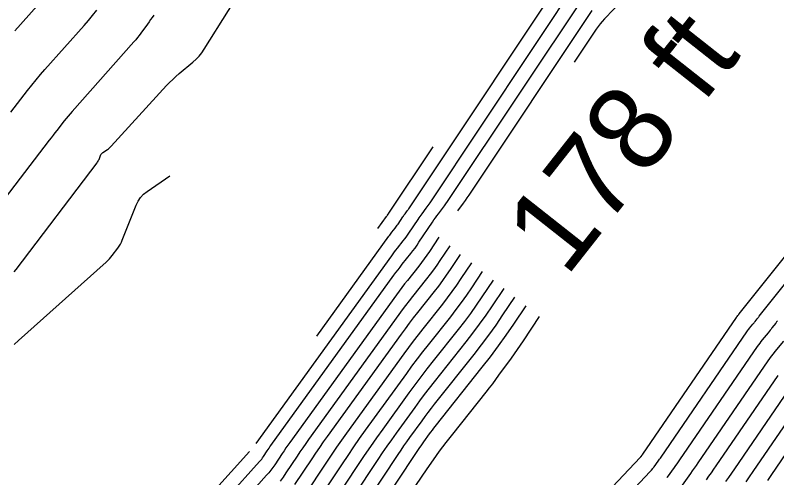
# Model space of a CAD drawing. Extents: x 7585033 to 7595090, y 547091 to 553471.
# Drawn here: x 7587211.1 to 7587267.7, y 547852.6 to 547887 of the extents above; entities that cross this region are included whole.
import ezdxf

# ---------------------------------------------------------------- set-up
doc = ezdxf.new("R2010")
doc.units = 0
for name, color, linetype in [('E_TERR_DSPLAY_GeneralTx', 7, 'Continuous'), ('E_TERR_DSPLAY_MajContour', 7, 'Continuous'), ('E_TERR_DSPLAY_MinContour', 7, 'Continuous')]:
    doc.layers.add(name, color=color, linetype=linetype)

msp = doc.modelspace()

# ---------------------------------------------------------------- linework, layer by layer
at = {"layer": 'E_TERR_DSPLAY_MajContour'}
for points in [[(7587253.285, 547890.138), (7587241.908, 547873.053), (7587241.836, 547872.947), (7587241.763, 547872.843), (7587241.689, 547872.739), (7587241.613, 547872.637), (7587241.306, 547872.229), (7587241.23, 547872.126), (7587241.156, 547872.023), (7587241.082, 547871.918), (7587241.011, 547871.813), (7587240.324, 547870.785), (7587240.226, 547870.641), (7587240.124, 547870.499), (7587240.02, 547870.359), (7587239.912, 547870.221), (7587239.477, 547869.673), (7587239.369, 547869.536), (7587239.262, 547869.397), (7587239.157, 547869.257), (7587239.054, 547869.116), (7587228.97, 547855.173)], [(7587211.064, 547885.809), (7587212.715, 547887.662)], [(7587211.012, 547862.513), (7587211.35, 547862.826), (7587217.852, 547868.647), (7587217.976, 547868.763), (7587218.094, 547868.884), (7587218.205, 547869.011), (7587218.311, 547869.144), (7587218.722, 547869.685), (7587218.82, 547869.823), (7587218.907, 547869.966), (7587218.985, 547870.116), (7587219.052, 547870.271), (7587220.075, 547872.862), (7587220.22, 547873.165), (7587220.405, 547873.437), (7587220.63, 547873.677), (7587220.894, 547873.886), (7587222.596, 547875.043)], [(7587231.884, 547852.131), (7587233.158, 547854.048), (7587233.438, 547854.467), (7587233.723, 547854.882), (7587234.013, 547855.295), (7587234.306, 547855.704), (7587239.794, 547863.294), (7587240.091, 547863.699), (7587240.392, 547864.101), (7587240.698, 547864.499), (7587241.009, 547864.894), (7587242.26, 547866.466), (7587242.568, 547866.863), (7587242.868, 547867.265), (7587243.16, 547867.673), (7587243.443, 547868.088), (7587244.199, 547869.219)], [(7587234.41, 547848.472), (7587238.072, 547853.985), (7587238.402, 547854.477), (7587238.737, 547854.966), (7587239.078, 547855.452), (7587239.423, 547855.934), (7587240.812, 547857.856), (7587241.163, 547858.334), (7587241.518, 547858.808), (7587241.879, 547859.278), (7587242.246, 547859.744), (7587244.607, 547862.712), (7587245.117, 547863.366), (7587245.612, 547864.031), (7587246.094, 547864.706), (7587246.562, 547865.39), (7587247.422, 547866.678)], [(7587268.184, 547862.77), (7587267.553, 547862.007), (7587267.415, 547861.836), (7587267.281, 547861.663), (7587267.151, 547861.487), (7587267.025, 547861.307), (7587261.834, 547853.735), (7587261.696, 547853.535), (7587261.556, 547853.336), (7587261.415, 547853.138), (7587261.273, 547852.941), (7587260.529, 547851.919)], [(7587270.134, 547856.995), (7587267.306, 547852.87), (7587267, 547852.428)], [(7587228.495, 547854.582), (7587225.771, 547851.56), (7587225.725, 547851.507), (7587225.681, 547851.454), (7587225.638, 547851.399), (7587225.597, 547851.344), (7587225.434, 547851.118), (7587225.394, 547851.062), (7587225.353, 547851.005), (7587225.313, 547850.949), (7587225.272, 547850.893), (7587213.854, 547834.973), (7587213.662, 547834.713), (7587213.464, 547834.46), (7587213.258, 547834.212), (7587213.046, 547833.969), (7587212.181, 547833.011), (7587211.966, 547832.77), (7587211.754, 547832.527), (7587211.545, 547832.282), (7587211.338, 547832.034), (7587205.238, 547824.638)]]:
    msp.add_lwpolyline(points, dxfattribs=at)
at = {"layer": 'E_TERR_DSPLAY_MinContour'}
for points in [[(7587233.505, 547863.154), (7587238.869, 547870.572), (7587238.924, 547870.647), (7587238.98, 547870.721), (7587239.036, 547870.795), (7587239.094, 547870.868), (7587239.325, 547871.159), (7587239.383, 547871.233), (7587239.438, 547871.307), (7587239.492, 547871.383), (7587239.545, 547871.46), (7587239.91, 547872.006), (7587239.948, 547872.062), (7587239.987, 547872.118), (7587240.026, 547872.173), (7587240.067, 547872.227), (7587240.23, 547872.444), (7587240.27, 547872.499), (7587240.31, 547872.554), (7587240.349, 547872.61), (7587240.387, 547872.666), (7587252.955, 547891.539)], [(7587258.388, 547890.774), (7587257.674, 547889.983), (7587257.485, 547889.77), (7587257.301, 547889.553), (7587257.12, 547889.332), (7587256.944, 547889.108), (7587256.196, 547888.139), (7587256.045, 547887.948), (7587255.888, 547887.761), (7587255.726, 547887.578), (7587255.56, 547887.4), (7587254.884, 547886.694), (7587254.719, 547886.514), (7587254.563, 547886.328), (7587254.415, 547886.135), (7587254.275, 547885.935), (7587252.643, 547883.483)], [(7587211.013, 547867.91), (7587211.158, 547868.093), (7587217.173, 547876.01), (7587217.217, 547876.072), (7587217.257, 547876.137), (7587217.291, 547876.204), (7587217.322, 547876.273), (7587217.434, 547876.557), (7587217.466, 547876.625), (7587217.507, 547876.685), (7587217.557, 547876.739), (7587217.616, 547876.785), (7587217.946, 547877.009), (7587218.02, 547877.063), (7587218.091, 547877.121), (7587218.158, 547877.183), (7587218.222, 547877.248), (7587222.344, 547881.746), (7587222.569, 547881.983), (7587222.801, 547882.212), (7587223.041, 547882.433), (7587223.289, 547882.646), (7587224.295, 547883.482), (7587224.536, 547883.7), (7587224.758, 547883.934), (7587224.961, 547884.186), (7587225.144, 547884.455), (7587228.745, 547890.212)], [(7587226.897, 547851.217), (7587229.255, 547853.833), (7587229.335, 547853.925), (7587229.411, 547854.019), (7587229.483, 547854.117), (7587229.552, 547854.217), (7587229.821, 547854.621), (7587229.889, 547854.722), (7587229.958, 547854.823), (7587230.027, 547854.922), (7587230.098, 547855.021), (7587239.239, 547867.661), (7587239.391, 547867.868), (7587239.545, 547868.073), (7587239.701, 547868.277), (7587239.86, 547868.478), (7587240.499, 547869.282), (7587240.657, 547869.485), (7587240.81, 547869.69), (7587240.959, 547869.899), (7587241.104, 547870.111), (7587242.112, 547871.619), (7587242.217, 547871.774), (7587242.324, 547871.928), (7587242.434, 547872.08), (7587242.545, 547872.23), (7587242.996, 547872.829), (7587243.107, 547872.979), (7587243.217, 547873.131), (7587243.324, 547873.285), (7587243.429, 547873.44), (7587253.615, 547888.737)], [(7587210.762, 547879.786), (7587212.005, 547881.387), (7587212.319, 547881.784), (7587212.64, 547882.176), (7587212.967, 547882.563), (7587213.301, 547882.944), (7587216.216, 547886.215), (7587216.537, 547886.584), (7587216.848, 547886.962), (7587217.148, 547887.347)], [(7587253.945, 547887.336), (7587244.949, 547873.827), (7587244.811, 547873.623), (7587244.67, 547873.42), (7587244.526, 547873.22), (7587244.379, 547873.021), (7587243.958, 547872.462)], [(7587221.396, 547886.985), (7587221.277, 547886.815), (7587221.158, 547886.647), (7587221.039, 547886.478), (7587220.918, 547886.31), (7587220.436, 547885.638), (7587220.314, 547885.472), (7587220.187, 547885.31), (7587220.056, 547885.15), (7587219.92, 547884.994), (7587215.317, 547879.83), (7587215.168, 547879.659), (7587215.022, 547879.486), (7587214.878, 547879.311), (7587214.738, 547879.133), (7587214.181, 547878.417), (7587214.042, 547878.238), (7587213.904, 547878.059), (7587213.765, 547877.879), (7587213.627, 547877.699), (7587208.496, 547871.011)], [(7587252.589, 547848.886), (7587257.541, 547854.13), (7587257.547, 547854.137), (7587257.553, 547854.143), (7587257.559, 547854.15), (7587257.564, 547854.157), (7587257.587, 547854.186), (7587257.598, 547854.2), (7587257.609, 547854.215), (7587257.678, 547854.31), (7587257.691, 547854.329), (7587257.704, 547854.347), (7587257.717, 547854.366), (7587257.73, 547854.384), (7587264.694, 547864.541), (7587264.705, 547864.557), (7587264.717, 547864.573), (7587264.728, 547864.588), (7587264.741, 547864.603), (7587264.796, 547864.67), (7587264.805, 547864.681), (7587264.814, 547864.692), (7587264.823, 547864.703), (7587264.832, 547864.714), (7587264.866, 547864.759), (7587264.884, 547864.782), (7587264.902, 547864.804), (7587279.275, 547882.751)], [(7587253.765, 547848.293), (7587258.293, 547853.089), (7587258.319, 547853.117), (7587258.345, 547853.146), (7587258.37, 547853.175), (7587258.394, 547853.205), (7587258.489, 547853.327), (7587258.513, 547853.357), (7587258.536, 547853.388), (7587258.559, 547853.419), (7587258.582, 547853.45), (7587258.876, 547853.854), (7587258.932, 547853.932), (7587258.988, 547854.01), (7587259.043, 547854.089), (7587259.098, 547854.168), (7587265.471, 547863.463), (7587265.521, 547863.534), (7587265.572, 547863.603), (7587265.624, 547863.671), (7587265.678, 547863.737), (7587265.925, 547864.037), (7587265.966, 547864.086), (7587266.006, 547864.135), (7587266.045, 547864.185), (7587266.084, 547864.235), (7587266.24, 547864.436), (7587266.279, 547864.486), (7587266.319, 547864.536), (7587266.358, 547864.586), (7587266.398, 547864.636), (7587279.695, 547881.239)], [(7587238.039, 547871.136), (7587238.684, 547872.027), (7587238.69, 547872.036), (7587238.697, 547872.045), (7587238.704, 547872.054), (7587238.711, 547872.063), (7587238.739, 547872.098), (7587238.745, 547872.107), (7587238.752, 547872.116), (7587238.759, 547872.125), (7587238.765, 547872.134), (7587238.809, 547872.2), (7587238.818, 547872.213), (7587238.828, 547872.226), (7587238.847, 547872.252), (7587238.857, 547872.265), (7587238.866, 547872.279), (7587242.148, 547877.206)], [(7587242.587, 547870.489), (7587241.884, 547869.437), (7587241.693, 547869.157), (7587241.496, 547868.882), (7587241.294, 547868.611), (7587241.086, 547868.344), (7587240.243, 547867.284), (7587240.033, 547867.018), (7587239.827, 547866.749), (7587239.624, 547866.478), (7587239.424, 547866.205), (7587231.501, 547855.249), (7587231.356, 547855.046), (7587231.213, 547854.842), (7587231.072, 547854.637), (7587230.933, 547854.43), (7587230.382, 547853.601), (7587230.241, 547853.396), (7587230.092, 547853.197), (7587229.937, 547853.004), (7587229.774, 547852.816), (7587228.024, 547850.874)], [(7587243.393, 547869.854), (7587242.663, 547868.762), (7587242.426, 547868.415), (7587242.182, 547868.073), (7587241.931, 547867.737), (7587241.673, 547867.405), (7587240.626, 547866.089), (7587240.366, 547865.758), (7587240.11, 547865.425), (7587239.858, 547865.089), (7587239.609, 547864.75), (7587232.903, 547855.477), (7587232.684, 547855.171), (7587232.468, 547854.862), (7587232.255, 547854.552), (7587232.046, 547854.239), (7587231.212, 547852.985), (7587230.999, 547852.676), (7587230.774, 547852.375)], [(7587245.005, 547868.583), (7587244.223, 547867.414), (7587243.893, 547866.931), (7587243.554, 547866.456), (7587243.205, 547865.989), (7587242.846, 547865.528), (7587241.392, 547863.699), (7587241.031, 547863.24), (7587240.675, 547862.777), (7587240.325, 547862.31), (7587239.98, 547861.838), (7587235.708, 547855.932), (7587235.341, 547855.419), (7587234.979, 547854.902), (7587234.622, 547854.381), (7587234.27, 547853.857), (7587232.516, 547851.217)], [(7587245.811, 547867.948), (7587245.003, 547866.739), (7587244.627, 547866.189), (7587244.24, 547865.648), (7587243.842, 547865.115), (7587243.433, 547864.589), (7587241.775, 547862.505), (7587241.363, 547861.981), (7587240.957, 547861.453), (7587240.558, 547860.92), (7587240.165, 547860.383), (7587237.111, 547856.16), (7587236.669, 547855.543), (7587236.234, 547854.922), (7587235.805, 547854.296), (7587235.382, 547853.666), (7587233.147, 547850.302)], [(7587246.617, 547867.313), (7587245.782, 547866.065), (7587245.361, 547865.448), (7587244.926, 547864.839), (7587244.479, 547864.241), (7587244.02, 547863.651), (7587242.158, 547861.31), (7587241.695, 547860.722), (7587241.24, 547860.129), (7587240.791, 547859.531), (7587240.35, 547858.927), (7587238.413, 547856.249), (7587237.947, 547855.598), (7587237.488, 547854.943), (7587237.035, 547854.283), (7587236.589, 547853.618), (7587233.779, 547849.387)], [(7587235.041, 547847.557), (7587239.554, 547854.352), (7587239.769, 547854.672), (7587239.987, 547854.99), (7587240.208, 547855.306), (7587240.433, 547855.619), (7587241.336, 547856.869), (7587241.564, 547857.18), (7587241.795, 547857.488), (7587242.03, 547857.794), (7587242.268, 547858.097), (7587245.194, 547861.774), (7587245.754, 547862.492), (7587246.298, 547863.223), (7587246.828, 547863.964), (7587247.342, 547864.716), (7587248.228, 547866.043)], [(7587249.034, 547865.408), (7587248.121, 547864.042), (7587247.561, 547863.222), (7587246.984, 547862.414), (7587246.391, 547861.618), (7587245.781, 547860.835), (7587242.291, 547856.449), (7587242.181, 547856.309), (7587242.073, 547856.168), (7587241.966, 547856.026), (7587241.861, 547855.882), (7587241.443, 547855.304), (7587241.339, 547855.159), (7587241.237, 547855.014), (7587241.136, 547854.867), (7587241.037, 547854.719), (7587235.673, 547846.642)], [(7587250.042, 547864.614), (7587248.845, 547862.795), (7587248.627, 547862.469), (7587248.406, 547862.146), (7587248.18, 547861.825), (7587247.951, 547861.507), (7587247.024, 547860.242), (7587246.791, 547859.927), (7587246.555, 547859.614), (7587246.315, 547859.303), (7587246.073, 547858.995), (7587243.583, 547855.866), (7587243.092, 547855.237), (7587242.613, 547854.6), (7587242.147, 547853.955), (7587241.692, 547853.3), (7587237.844, 547847.656)], [(7587267.753, 547864.291), (7587267.684, 547864.202), (7587267.614, 547864.113), (7587267.337, 547863.756), (7587267.268, 547863.667), (7587267.197, 547863.579), (7587267.127, 547863.491), (7587267.055, 547863.403), (7587266.615, 547862.872), (7587266.52, 547862.754), (7587266.426, 547862.633), (7587266.336, 547862.51), (7587266.248, 547862.385), (7587260.466, 547853.952), (7587260.37, 547853.812), (7587260.272, 547853.673), (7587260.174, 547853.535), (7587260.074, 547853.397), (7587259.555, 547852.684), (7587259.515, 547852.629)], [(7587262.471, 547852.485), (7587262.656, 547852.741), (7587262.84, 547852.999), (7587263.022, 547853.259), (7587263.202, 547853.519), (7587267.803, 547860.229)], [(7587263.898, 547852.345), (7587264.124, 547852.662), (7587264.348, 547852.982), (7587264.57, 547853.303), (7587268.58, 547859.151)], [(7587265.408, 547852.325), (7587265.674, 547852.705), (7587265.938, 547853.087), (7587269.357, 547858.073)]]:
    msp.add_lwpolyline(points, dxfattribs=at)

# ---------------------------------------------------------------- texts
at = {"layer": 'E_TERR_DSPLAY_GeneralTx'}
msp.add_text('178 ft', height=6.3, rotation=51.7616, dxfattribs=at).set_placement((7587252.038, 547867.448))

doc.saveas('drawing.dxf')
